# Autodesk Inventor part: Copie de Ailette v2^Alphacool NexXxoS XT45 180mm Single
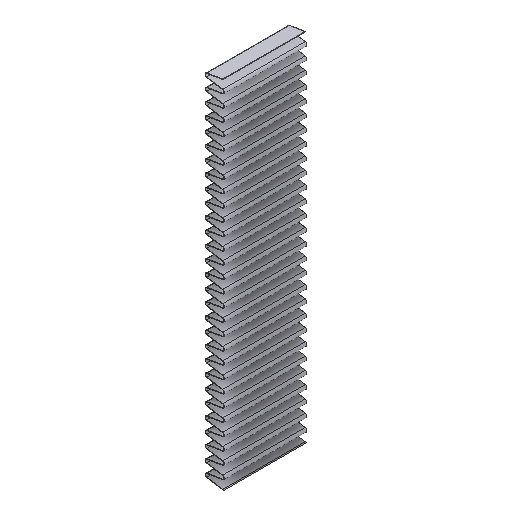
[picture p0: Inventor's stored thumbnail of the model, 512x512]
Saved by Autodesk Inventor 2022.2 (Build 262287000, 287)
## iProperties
Created: 2015-05
Part Number: Copie de Ailette v2^Alphacool NexXxoS XT45 180mm Single
Material: Generico
Document SubType Name: Modeling
Designer: 18907419
Density: 1 g/cm^3
Appearance: Default
Author: 18907419
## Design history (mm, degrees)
feature "Solido1"
node "Solido2"
